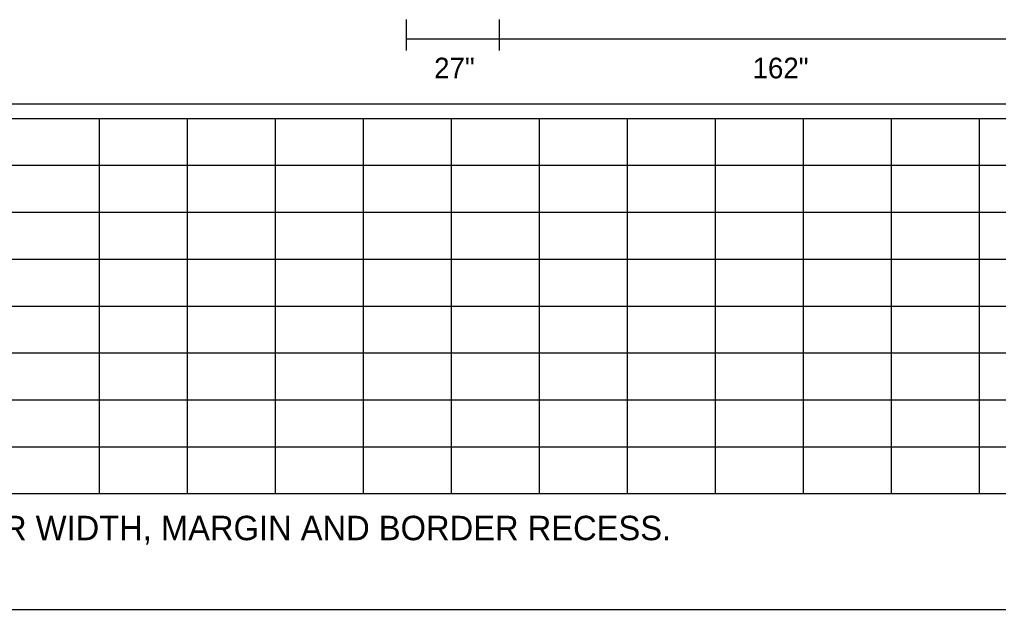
# Model space of a CAD drawing. Extents: x 10268312 to 10268706, y 2142548 to 2142786.
# Drawn here: x 10268420.26 to 10268453.64, y 2142640.28 to 2142660.4 of the extents above; entities that cross this region are included whole.
import ezdxf

# ---------------------------------------------------------------- set-up
doc = ezdxf.new("R2010")
doc.units = 0
for name, color, linetype in [('GSDims', 7, 'Continuous'), ('SheetBorder_dp', 7, 'Continuous'), ('SumBoxLines_dp', 7, 'Continuous'), ('SumBoxLinesMin_dp', 7, 'Continuous'), ('TextNotes', 7, 'Continuous')]:
    doc.layers.add(name, color=color, linetype=linetype)

msp = doc.modelspace()

# ---------------------------------------------------------------- linework, layer by layer
at = {"layer": 'GSDims'}
for p, q in [((10268433.445, 2142660.403), (10268433.445, 2142659.345)), ((10268436.62, 2142660.403), (10268436.62, 2142659.345)), ((10268433.445, 2142659.742), (10268436.62, 2142659.742)), ((10268436.62, 2142659.742), (10268455.67, 2142659.742))]:
    msp.add_line(p, q, dxfattribs=at)
at = {"layer": 'SheetBorder_dp'}
msp.add_line((10268317.73, 2142640.282), (10268471.73, 2142640.282), dxfattribs=at)
at = {"layer": 'SumBoxLines_dp'}
for p, q in [((10268418.73, 2142657.532), (10268470.98, 2142657.532)), ((10268395.48, 2142657.032), (10268470.98, 2142657.032)), ((10268422.98, 2142657.032), (10268422.98, 2142653.832)), ((10268425.98, 2142657.032), (10268425.98, 2142653.832)), ((10268428.98, 2142657.032), (10268428.98, 2142653.832)), ((10268431.98, 2142657.032), (10268431.98, 2142653.832)), ((10268434.98, 2142657.032), (10268434.98, 2142655.432)), ((10268437.98, 2142657.032), (10268437.98, 2142655.432)), ((10268440.98, 2142657.032), (10268440.98, 2142653.832)), ((10268443.98, 2142657.032), (10268443.98, 2142653.832)), ((10268446.98, 2142657.032), (10268446.98, 2142655.432)), ((10268449.98, 2142657.032), (10268449.98, 2142655.432)), ((10268452.98, 2142657.032), (10268452.98, 2142655.432)), ((10268434.98, 2142655.432), (10268434.98, 2142649.032)), ((10268437.98, 2142655.432), (10268437.98, 2142647.432)), ((10268440.98, 2142655.432), (10268440.98, 2142647.432)), ((10268443.98, 2142655.432), (10268443.98, 2142649.032)), ((10268446.98, 2142655.432), (10268446.98, 2142649.032)), ((10268449.98, 2142655.432), (10268449.98, 2142644.232)), ((10268452.98, 2142655.432), (10268452.98, 2142644.232)), ((10268395.48, 2142653.832), (10268470.98, 2142653.832)), ((10268422.98, 2142653.832), (10268422.98, 2142650.632)), ((10268425.98, 2142653.832), (10268425.98, 2142650.632)), ((10268428.98, 2142653.832), (10268428.98, 2142650.632)), ((10268431.98, 2142653.832), (10268431.98, 2142649.032)), ((10268395.48, 2142650.632), (10268470.98, 2142650.632)), ((10268422.98, 2142650.632), (10268422.98, 2142647.432)), ((10268425.98, 2142650.632), (10268425.98, 2142647.432)), ((10268428.98, 2142650.632), (10268428.98, 2142647.432)), ((10268431.98, 2142649.032), (10268431.98, 2142644.232)), ((10268434.98, 2142649.032), (10268434.98, 2142644.232)), ((10268443.98, 2142649.032), (10268443.98, 2142644.232)), ((10268446.98, 2142649.032), (10268446.98, 2142644.232)), ((10268395.48, 2142647.432), (10268470.98, 2142647.432)), ((10268422.98, 2142647.432), (10268422.98, 2142644.232)), ((10268425.98, 2142647.432), (10268425.98, 2142644.232)), ((10268428.98, 2142647.432), (10268428.98, 2142644.232)), ((10268437.98, 2142647.432), (10268437.98, 2142644.232)), ((10268440.98, 2142647.432), (10268440.98, 2142644.232)), ((10268395.48, 2142644.232), (10268470.98, 2142644.232))]:
    msp.add_line(p, q, dxfattribs=at)
at = {"layer": 'SumBoxLinesMin_dp'}
for p, q in [((10268395.48, 2142655.432), (10268470.98, 2142655.432)), ((10268395.48, 2142652.232), (10268470.98, 2142652.232)), ((10268395.48, 2142649.032), (10268470.98, 2142649.032)), ((10268395.48, 2142645.832), (10268470.98, 2142645.832))]:
    msp.add_line(p, q, dxfattribs=at)

# ---------------------------------------------------------------- texts
at = {"layer": 'GSDims'}
for s, p in [('27"', (10268434.399, 2142658.398)), ('162"', (10268445.259, 2142658.398))]:
    msp.add_text(s, height=0.7056, dxfattribs=at).set_placement(p)
at = {"layer": 'TextNotes'}
msp.add_text('NOTE:  END DIMENSIONS INCLUDE BORDER WIDTH, MARGIN AND BORDER RECESS.  ', height=0.83333, dxfattribs=at).set_placement((10268396.479, 2142642.643))

doc.saveas('drawing.dxf')
